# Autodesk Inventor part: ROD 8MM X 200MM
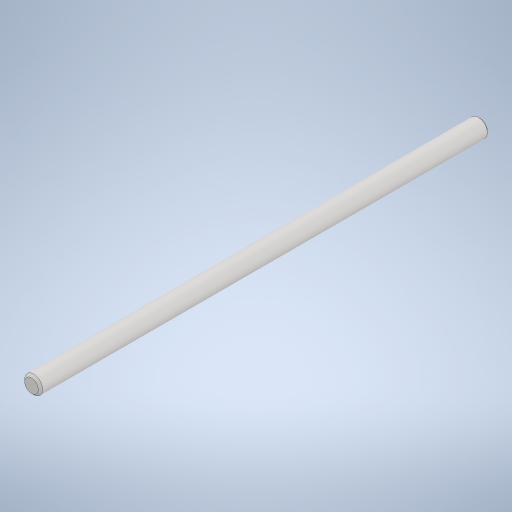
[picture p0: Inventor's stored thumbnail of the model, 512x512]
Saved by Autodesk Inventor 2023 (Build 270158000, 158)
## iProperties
Created: 2025-07
Part Number: ROD 8MM X 200MM
Material: Generic
Document SubType Name: Modeling
Designer: erjon
Density: 1 g/cm^3
Appearance: Default
Author: erjon
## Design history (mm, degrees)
feature "Base1"
body "Solid1"
